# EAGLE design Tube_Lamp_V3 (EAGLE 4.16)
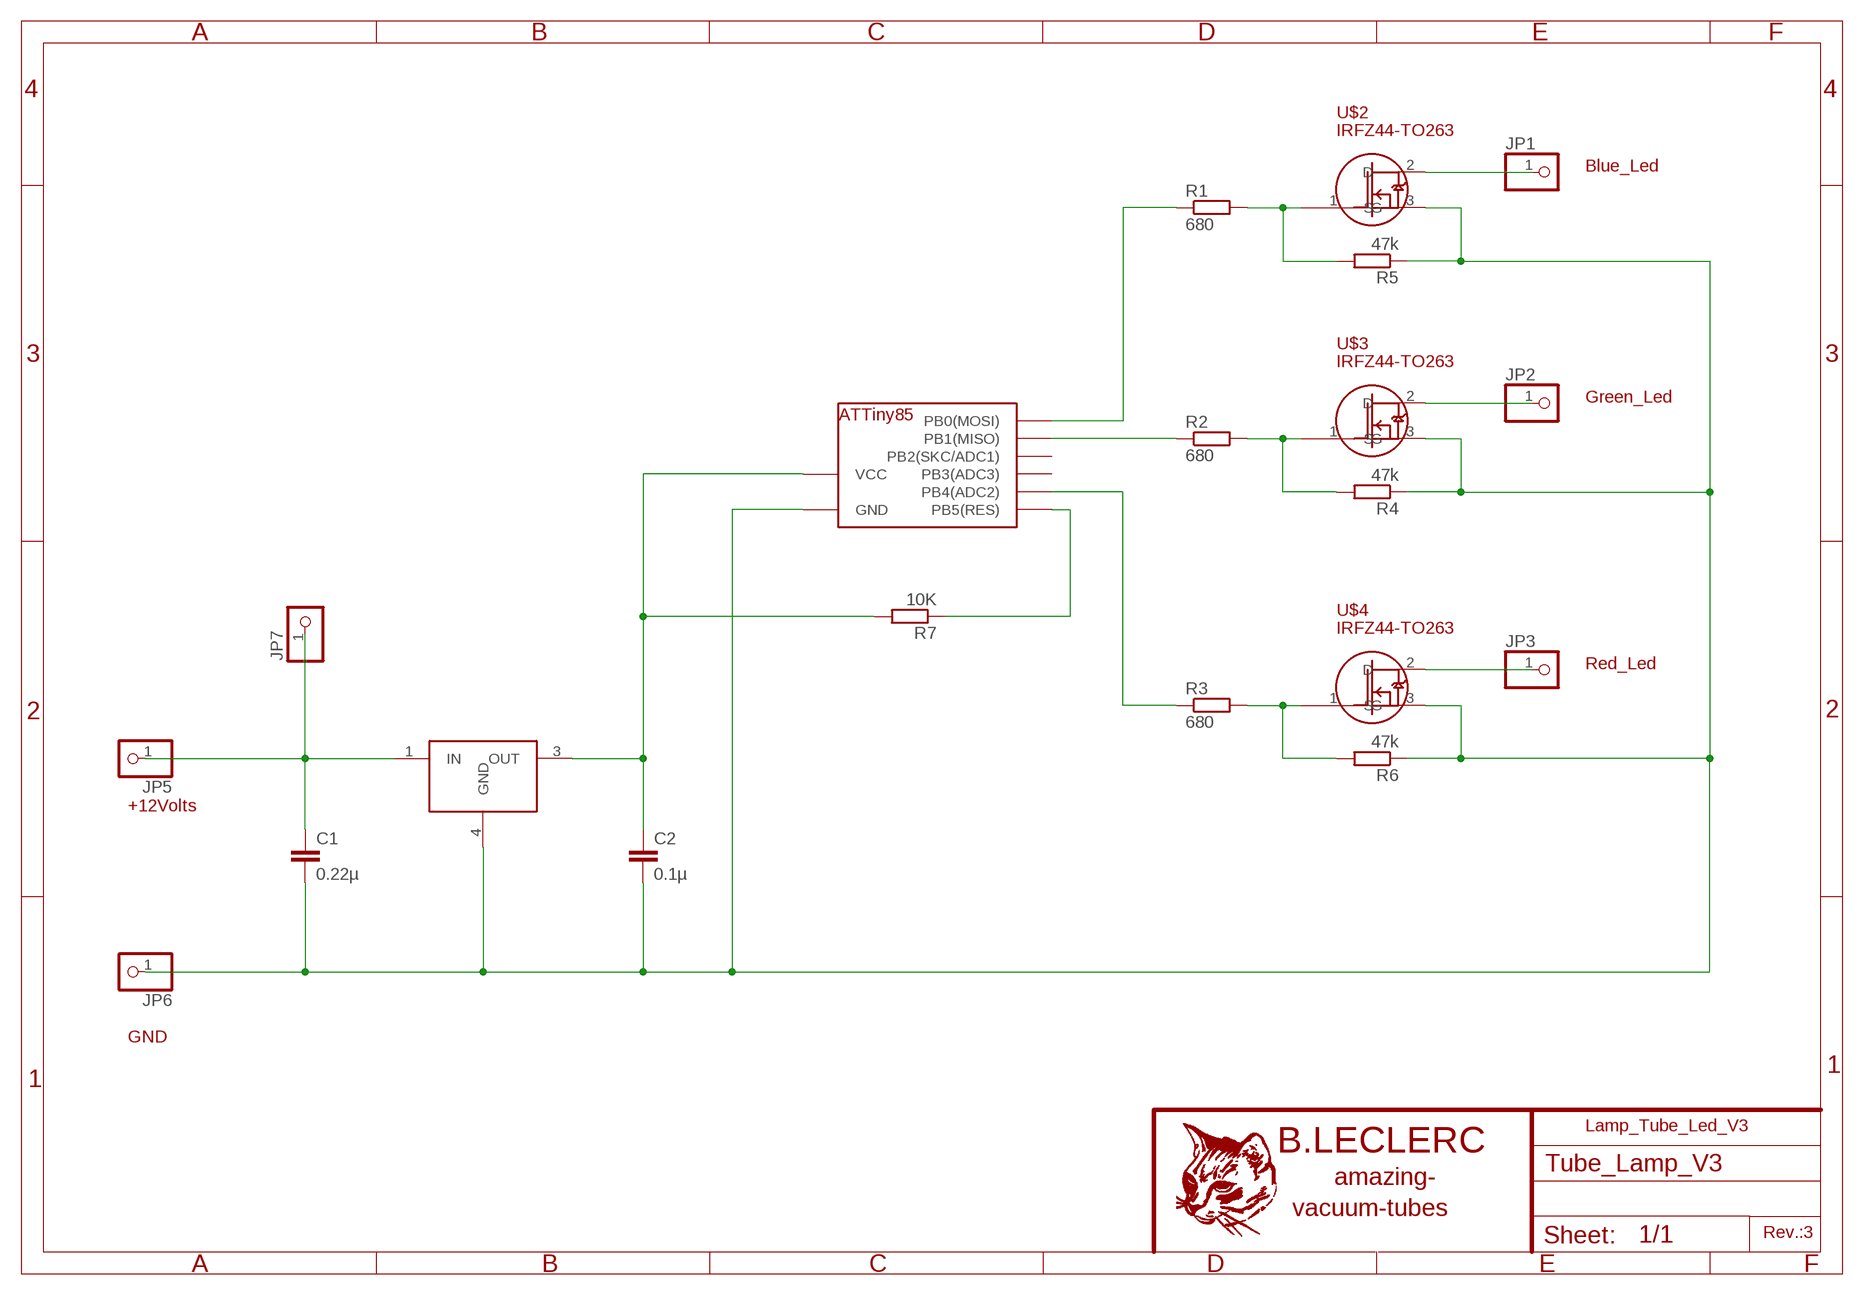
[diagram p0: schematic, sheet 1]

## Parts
C1  0.22µ  C-EUC1206K  [C1206K]
C2  0.1µ  C-EUC1206K  [C1206K]
JP1  PINHD-1X1  [1X01]
JP2  PINHD-1X1  [1X01]
JP3  PINHD-1X1  [1X01]
JP5  PINHD-1X1  [1X01]
JP6  PINHD-1X1  [1X01]
JP7  PINHD-1X1  [1X01]
R1  680  R-EU_M1206  [M1206]
R2  680  R-EU_M1206  [M1206]
R3  680  R-EU_M1206  [M1206]
R4  47k  R-EU_M1206  [M1206]
R5  47k  R-EU_M1206  [M1206]
R6  47k  R-EU_M1206  [M1206]
R7  10K  R-EU_M1206  [M1206]
U1  7805  MINI78XX  [DPACK]
U$2  IRFZ44-TO263  [TO263]
U$3  IRFZ44-TO263  [TO263]
U$4  IRFZ44-TO263  [TO263]
U$5  ATTINY85  [DIL08]

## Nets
N$1: R1.1 U$5.5(PB0(MOSI))
N$2: R2.1 U$5.6(PB1(MISO))
N$3: R3.1 U$5.3(PB4(ADC2))
N$4: R1.2 R5.2 U$2.1(G)
N$5: R2.2 R4.2 U$3.1(G)
N$6: R3.2 R6.2 U$4.1(G)
N$7: JP1.1 U$2.2(D)
N$8: JP2.1 U$3.2(D)
N$9: JP3.1 U$4.2(D)
N$13: R7.1 U$5.1(PB5(RES))
N$14: C1.1 JP5.1 JP7.1 U1.1(IN)
N$15: C2.1 R7.2 U1.3(OUT) U$5.8(VCC)
N£16: C1.2 C2.2 JP6.1 R4.1 R5.1 R6.1 U1.4(GND) U$2.3(S) U$3.3(S) U$4.3(S) U$5.4(GND)
Unconnected: U$5.2(PB3(ADC3)) U$5.7(PB2(SKC/ADC1))

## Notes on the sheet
- Blue_Led
- Green_Led
- Red_Led
- +12Volts
- GND
- Lamp_Tube_Led_V3
- Rev.:3

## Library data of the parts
C1 C2 = rcl:C-EU: CAPACITOR, European symbol
JP1-JP3 JP5-JP7 = pinhead:PINHD-1X1: PIN HEADER
R1-R7 = rcl:R-EU_: RESISTOR, European symbol
U1 = v-reg:MINI78XX
U$2-U$4 = transistor-fet:IRFZ44-TO263
U$5 = atmel:ATTINY85

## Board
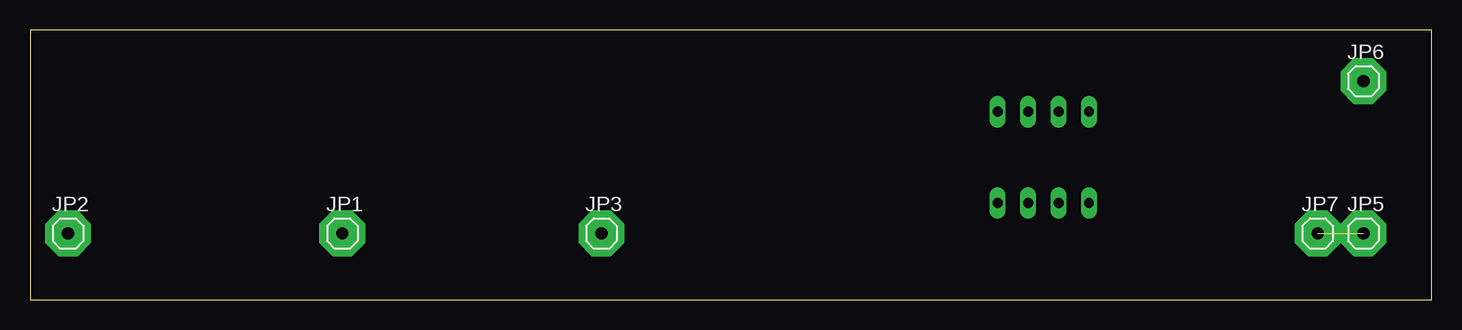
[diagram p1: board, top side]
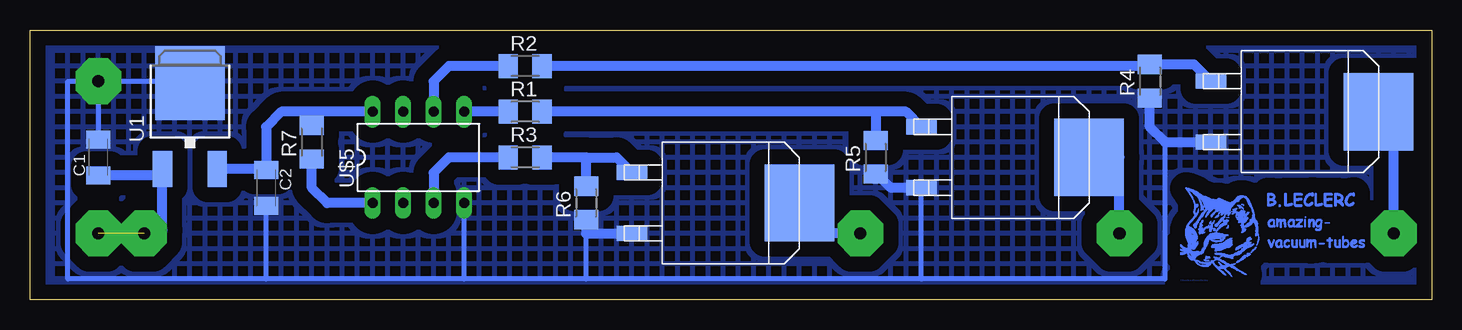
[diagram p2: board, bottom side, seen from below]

Size 116.82 x 22.53 mm. Coordinates in mm from the lower left corner, seen from the top.
Outline: 0,0 116.82,0 116.82,22.53 0,22.53 0,0
Copper layers (1*16): Top 0.035mm / dielectric 1.5mm / Bottom 0.035mm
Design rules "default": minimum track width 10mil, minimum drill 24mil, track to track 8mil, track to pad 8mil, pad to pad 8mil, via to via 8mil, smd to smd 8mil, copper to edge 40mil, drill to drill 8mil, minimum pad ring 10mil, minimum via ring 8mil, stop-mask expansion 4mil, vias tented up to drill 0mil, thermal gap 10mil

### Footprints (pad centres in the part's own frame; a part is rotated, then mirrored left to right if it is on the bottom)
C1206K = smd 1.5 x 2: 1 -1.5,0; 2 1.5,0
1X01 = drill 1.016 octagon: 1 0,0
M1206 = smd 1.6 x 2: 1 -1.4,0; 2 1.4,0
DPACK = smd 1.6 x 3: 1 -2.28,-4.8; 3 2.28,-4.8 | smd 5.8 x 6.2: 4 0,2.38
TO263 = smd 2.54 x 1.27: 1 0,2.54; 3 0,-2.54 | smd 3.251 x 6.452: 2 15.24,0; P$3 12.7,0
DIL08 = drill 0.813 long: 1 -3.81,-3.81; 2 -1.27,-3.81; 3 1.27,-3.81; 4 3.81,-3.81; 5 3.81,3.81; 6 1.27,3.81; 7 -1.27,3.81; 8 -3.81,3.81

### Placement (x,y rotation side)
C1  111.12,11.9 90 bottom
C2  97.15,9.36 270 bottom
JP1  26.03,5.55 0 top
JP2  3.17,5.55 0 top
JP3  47.62,5.55 0 top
JP5  111.12,5.55 0 top
JP6  111.12,18.25 0 top
JP7  107.31,5.55 0 top
R1  75.56,15.71 0 bottom
R2  75.56,19.52 0 bottom
R3  75.56,11.9 0 bottom
R4  23.49,18.25 90 bottom
R5  46.35,11.9 90 bottom
R6  70.48,8.09 90 bottom
R7  93.34,13.17 90 bottom
U1  103.5,15.71 0 bottom
U$2  42.54,11.9 0 bottom
U$3  18.41,15.71 0 bottom
U$4  66.67,8.09 0 bottom
U$5  84.45,11.9 0 bottom
U$6  [CHAT]  20.95,1.74 0 bottom

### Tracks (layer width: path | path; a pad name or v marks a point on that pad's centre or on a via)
N$1
  Bottom 0.813: 76.83,15.71 R1.1 U$5.5
N$2
  Bottom 0.813: R2.1 81.91,19.52 83.18,18.25 U$5.6
N$3
  Bottom 0.813: U$5.3 83.18,10.63 81.91,11.9 R3.1 76.83,11.9
N$4
  Bottom 0.813: 46.35,15.71 43.81,15.71 U$2.1 | 46.35,15.71 R1.2 | 46.35,15.71 R5.2
N$5
  Bottom 0.813: R2.2 23.49,19.52 R4.2 19.81,19.65 U$3.1
N$6
  Bottom 0.813: 70.48,11.9 67.94,11.9 U$4.1 | 70.48,11.9 R3.2 | R6.2 70.48,11.9
N$7
  Bottom 0.406: 26.03,11.9 U$2.2
  Bottom 0.813: JP1.1 26.03,11.9
N$8
  Bottom 0.813: JP2.1 U$3.2
N$9
  Bottom 0.813: JP3.1 51.43,5.55 U$4.2
N$10  (via drill 0.5 pad 3.81)
  other vias: 3.17,5.55
N$11  (via drill 0.5 pad 3.81)
  other vias: 47.62,5.55
N$13
  Bottom 0.813: R7.1 93.34,9.36 92.07,8.09 U$5.1
N$14
  Bottom 0.813: JP5.1 JP7.1 106.04,5.55 105.78,5.81 U1.1 105.78,10.89 106.27,10.4 C1.1
N$15
  Bottom 0.813: U$5.8 93.34,15.71 | 93.34,15.71 95.88,15.71 97.15,14.44 C2.1 97.15,10.63 97.43,10.91 U1.3 | 93.34,15.71 R7.2
N$16  (via drill 0.5 pad 3.81)  (1 unrouted)
  other vias: 111.12,5.55 107.31,5.55
N$17  (via drill 0.5 pad 3.81)
  other vias: 26.03,5.55
N$19  (via drill 0.5 pad 1.27)
  other vias: 83.18,15.71
N$20  (via drill 0.5 pad 1.27)
  other vias: 80.64,15.71
N$21  (via drill 0.5 pad 1.27)
  other vias: 85.72,15.71
N$22  (via drill 0.5 pad 1.27)
  other vias: 83.18,8.09
N$23  (via drill 0.5 pad 1.27)
  other vias: 88.26,8.09 88.26,8.09
N$25  (via drill 0.5 pad 1.27)
  other vias: 88.26,15.71
N£16  (via drill 0.5 pad 1.27, 0.5 pad 3.81)
  Bottom 0.406: 80.64,1.74 U$5.4 | 42.54,1.74 70.48,1.74 | 70.48,1.74 80.64,1.74 | 42.54,1.74 22.22,1.74 22.22,13.17 | 42.54,1.74 U$2.3 | 70.48,1.74 R6.1 | 97.15,1.74 C2.2 | 80.64,1.74 97.15,1.74 | JP6.1 103.5,18.25 | JP6.1 113.66,18.25 113.66,1.74 97.15,1.74 | JP6.1 C1.2
  Bottom 0.813: U$3.3 22.22,13.17 23.49,14.44 R4.1 23.49,16.98 | R5.1 46.35,10.63 45.08,9.36 U$2.3 | U$4.3 70.48,5.55 R6.1 70.48,6.82 | 103.5,18.25 U1.4 | C1.2 111.12,13.17
  other vias: 80.64,8.09 111.12,18.25 111.12,18.25 111.12,18.25
  pour Bottom (isolate 1.27, no thermals, hatched): 0.63,22.06 116.2,22.06 116.2,0.47 0.63,0.47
